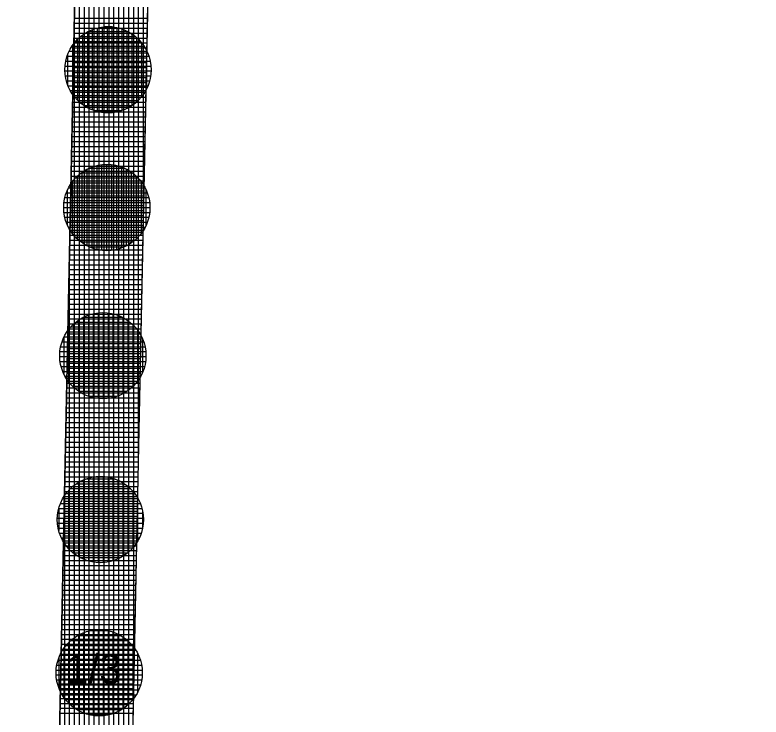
# Model space of a CAD drawing. Extents: x -566461 to -565198, y -1096301 to -1095707.
# Drawn here: x -565645.08 to -565614.79, y -1095920.77 to -1095892.27 of the extents above; entities that cross this region are included whole.
import ezdxf

# ---------------------------------------------------------------- set-up
doc = ezdxf.new("R2010")
doc.units = 0
for name, color, linetype in [('Vrstva 1', 7, 'Continuous'), ('Vrstva 40', 7, 'Continuous'), ('Vrstva 43', 7, 'Continuous'), ('Vrstva 44', 7, 'Continuous')]:
    doc.layers.add(name, color=color, linetype=linetype)

msp = doc.modelspace()

# ---------------------------------------------------------------- linework, layer by layer
at = {"layer": 'Vrstva 1'}
for p, q in [((-565645.08, -1096008.78), (-565642.52, -1095885.6)), ((-565642.11, -1096010.51), (-565639.56, -1095885.89))]:
    msp.add_line(p, q, dxfattribs=at)
at = {"layer": 'Vrstva 43'}
for p, q in [((-565642.06, -1096008.067), (-565642.06, -1095870.575)), ((-565641.86, -1095998.292), (-565641.86, -1095870.594)), ((-565641.66, -1095988.518), (-565641.66, -1095870.614)), ((-565641.46, -1095978.744), (-565641.46, -1095870.633)), ((-565641.26, -1095968.97), (-565641.26, -1095870.653)), ((-565641.06, -1095959.196), (-565641.06, -1095870.672)), ((-565640.86, -1095949.422), (-565640.86, -1095870.692)), ((-565640.66, -1095939.648), (-565640.66, -1095870.711)), ((-565640.46, -1095929.874), (-565640.46, -1095870.731)), ((-565640.26, -1095920.099), (-565640.26, -1095870.75)), ((-565640.06, -1095910.325), (-565640.06, -1095870.77)), ((-565639.86, -1095900.551), (-565639.86, -1095870.789)), ((-565642.26, -1096010.423), (-565642.26, -1095872.986)), ((-565642.46, -1096010.306), (-565642.46, -1095882.689)), ((-565642.662, -1095892.41), (-565639.693, -1095892.41)), ((-565642.66, -1096010.19), (-565642.66, -1095892.336)), ((-565642.666, -1095892.61), (-565639.698, -1095892.61)), ((-565642.674, -1095893.01), (-565639.706, -1095893.01)), ((-565642.67, -1095892.81), (-565639.702, -1095892.81)), ((-565642.678, -1095893.21), (-565639.71, -1095893.21)), ((-565642.686, -1095893.61), (-565639.718, -1095893.61)), ((-565642.682, -1095893.41), (-565639.714, -1095893.41)), ((-565642.691, -1095893.81), (-565639.722, -1095893.81)), ((-565642.699, -1095894.21), (-565639.73, -1095894.21)), ((-565642.695, -1095894.01), (-565639.726, -1095894.01)), ((-565642.703, -1095894.41), (-565639.734, -1095894.41)), ((-565642.711, -1095894.81), (-565639.743, -1095894.81)), ((-565642.707, -1095894.61), (-565639.738, -1095894.61)), ((-565642.716, -1095895.01), (-565639.747, -1095895.01)), ((-565642.724, -1095895.41), (-565639.755, -1095895.41)), ((-565642.72, -1095895.21), (-565639.751, -1095895.21)), ((-565642.728, -1095895.61), (-565639.759, -1095895.61)), ((-565642.736, -1095896.01), (-565639.767, -1095896.01)), ((-565642.732, -1095895.81), (-565639.763, -1095895.81)), ((-565642.741, -1095896.21), (-565639.771, -1095896.21)), ((-565642.749, -1095896.61), (-565639.779, -1095896.61)), ((-565642.745, -1095896.41), (-565639.775, -1095896.41)), ((-565642.753, -1095896.81), (-565639.783, -1095896.81)), ((-565642.761, -1095897.21), (-565639.792, -1095897.21)), ((-565642.757, -1095897.01), (-565639.788, -1095897.01)), ((-565642.765, -1095897.41), (-565639.796, -1095897.41)), ((-565642.774, -1095897.81), (-565639.804, -1095897.81)), ((-565642.77, -1095897.61), (-565639.8, -1095897.61)), ((-565642.778, -1095898.01), (-565639.808, -1095898.01)), ((-565642.786, -1095898.41), (-565639.816, -1095898.41)), ((-565642.782, -1095898.21), (-565639.812, -1095898.21)), ((-565642.79, -1095898.61), (-565639.82, -1095898.61)), ((-565642.799, -1095899.01), (-565639.828, -1095899.01)), ((-565642.795, -1095898.81), (-565639.824, -1095898.81)), ((-565642.803, -1095899.21), (-565639.833, -1095899.21)), ((-565642.811, -1095899.61), (-565639.841, -1095899.61)), ((-565642.807, -1095899.41), (-565639.837, -1095899.41)), ((-565642.815, -1095899.81), (-565639.845, -1095899.81)), ((-565642.824, -1095900.21), (-565639.853, -1095900.21)), ((-565642.819, -1095900.01), (-565639.849, -1095900.01)), ((-565642.832, -1095900.61), (-565639.861, -1095900.61)), ((-565642.828, -1095900.41), (-565639.857, -1095900.41)), ((-565642.836, -1095900.81), (-565639.865, -1095900.81)), ((-565642.844, -1095901.21), (-565639.873, -1095901.21)), ((-565642.84, -1095901.01), (-565639.869, -1095901.01)), ((-565642.849, -1095901.41), (-565639.878, -1095901.41)), ((-565642.857, -1095901.81), (-565639.886, -1095901.81)), ((-565642.853, -1095901.61), (-565639.882, -1095901.61)), ((-565642.861, -1095902.01), (-565639.89, -1095902.01)), ((-565642.86, -1096010.073), (-565642.86, -1095901.96)), ((-565642.869, -1095902.41), (-565639.898, -1095902.41)), ((-565642.865, -1095902.21), (-565639.894, -1095902.21)), ((-565642.874, -1095902.61), (-565639.902, -1095902.61)), ((-565642.882, -1095903.01), (-565639.91, -1095903.01)), ((-565642.878, -1095902.81), (-565639.906, -1095902.81)), ((-565642.886, -1095903.21), (-565639.914, -1095903.21)), ((-565642.894, -1095903.61), (-565639.923, -1095903.61)), ((-565642.89, -1095903.41), (-565639.918, -1095903.41)), ((-565642.898, -1095903.81), (-565639.927, -1095903.81)), ((-565642.907, -1095904.21), (-565639.935, -1095904.21)), ((-565642.903, -1095904.01), (-565639.931, -1095904.01)), ((-565642.911, -1095904.41), (-565639.939, -1095904.41)), ((-565642.919, -1095904.81), (-565639.947, -1095904.81)), ((-565642.915, -1095904.61), (-565639.943, -1095904.61)), ((-565642.923, -1095905.01), (-565639.951, -1095905.01)), ((-565642.932, -1095905.41), (-565639.959, -1095905.41)), ((-565642.928, -1095905.21), (-565639.955, -1095905.21)), ((-565642.936, -1095905.61), (-565639.964, -1095905.61)), ((-565642.944, -1095906.01), (-565639.972, -1095906.01)), ((-565642.94, -1095905.81), (-565639.968, -1095905.81)), ((-565642.948, -1095906.21), (-565639.976, -1095906.21)), ((-565642.957, -1095906.61), (-565639.984, -1095906.61)), ((-565642.952, -1095906.41), (-565639.98, -1095906.41)), ((-565642.961, -1095906.81), (-565639.988, -1095906.81)), ((-565642.969, -1095907.21), (-565639.996, -1095907.21)), ((-565642.965, -1095907.01), (-565639.992, -1095907.01)), ((-565642.973, -1095907.41), (-565640, -1095907.41)), ((-565642.982, -1095907.81), (-565640.009, -1095907.81)), ((-565642.977, -1095907.61), (-565640.004, -1095907.61)), ((-565642.986, -1095908.01), (-565640.013, -1095908.01)), ((-565642.994, -1095908.41), (-565640.021, -1095908.41)), ((-565642.99, -1095908.21), (-565640.017, -1095908.21)), ((-565642.998, -1095908.61), (-565640.025, -1095908.61)), ((-565643.007, -1095909.01), (-565640.033, -1095909.01)), ((-565643.002, -1095908.81), (-565640.029, -1095908.81)), ((-565643.011, -1095909.21), (-565640.037, -1095909.21)), ((-565643.019, -1095909.61), (-565640.045, -1095909.61)), ((-565643.015, -1095909.41), (-565640.041, -1095909.41)), ((-565643.023, -1095909.81), (-565640.049, -1095909.81)), ((-565643.031, -1095910.21), (-565640.058, -1095910.21)), ((-565643.027, -1095910.01), (-565640.054, -1095910.01)), ((-565643.036, -1095910.41), (-565640.062, -1095910.41)), ((-565643.044, -1095910.81), (-565640.07, -1095910.81)), ((-565643.04, -1095910.61), (-565640.066, -1095910.61)), ((-565643.052, -1095911.21), (-565640.078, -1095911.21)), ((-565643.048, -1095911.01), (-565640.074, -1095911.01)), ((-565643.056, -1095911.41), (-565640.082, -1095911.41)), ((-565643.065, -1095911.81), (-565640.09, -1095911.81)), ((-565643.061, -1095911.61), (-565640.086, -1095911.61)), ((-565643.06, -1096009.957), (-565643.06, -1095911.583)), ((-565643.069, -1095912.01), (-565640.094, -1095912.01)), ((-565643.077, -1095912.41), (-565640.103, -1095912.41)), ((-565643.073, -1095912.21), (-565640.099, -1095912.21)), ((-565643.081, -1095912.61), (-565640.107, -1095912.61)), ((-565643.09, -1095913.01), (-565640.115, -1095913.01)), ((-565643.085, -1095912.81), (-565640.111, -1095912.81)), ((-565643.094, -1095913.21), (-565640.119, -1095913.21)), ((-565643.102, -1095913.61), (-565640.127, -1095913.61)), ((-565643.098, -1095913.41), (-565640.123, -1095913.41)), ((-565643.106, -1095913.81), (-565640.131, -1095913.81)), ((-565643.115, -1095914.21), (-565640.139, -1095914.21)), ((-565643.11, -1095914.01), (-565640.135, -1095914.01)), ((-565643.119, -1095914.41), (-565640.144, -1095914.41)), ((-565643.127, -1095914.81), (-565640.152, -1095914.81)), ((-565643.123, -1095914.61), (-565640.148, -1095914.61)), ((-565643.131, -1095915.01), (-565640.156, -1095915.01)), ((-565643.14, -1095915.41), (-565640.164, -1095915.41)), ((-565643.135, -1095915.21), (-565640.16, -1095915.21)), ((-565643.144, -1095915.61), (-565640.168, -1095915.61)), ((-565643.152, -1095916.01), (-565640.176, -1095916.01)), ((-565643.148, -1095915.81), (-565640.172, -1095915.81)), ((-565643.156, -1095916.21), (-565640.18, -1095916.21)), ((-565643.164, -1095916.61), (-565640.189, -1095916.61)), ((-565643.16, -1095916.41), (-565640.185, -1095916.41)), ((-565643.169, -1095916.81), (-565640.193, -1095916.81)), ((-565643.177, -1095917.21), (-565640.201, -1095917.21)), ((-565643.173, -1095917.01), (-565640.197, -1095917.01)), ((-565643.181, -1095917.41), (-565640.205, -1095917.41)), ((-565643.189, -1095917.81), (-565640.213, -1095917.81)), ((-565643.185, -1095917.61), (-565640.209, -1095917.61)), ((-565643.194, -1095918.01), (-565640.217, -1095918.01)), ((-565643.202, -1095918.41), (-565640.225, -1095918.41)), ((-565643.198, -1095918.21), (-565640.221, -1095918.21)), ((-565643.206, -1095918.61), (-565640.23, -1095918.61)), ((-565643.214, -1095919.01), (-565640.238, -1095919.01)), ((-565643.21, -1095918.81), (-565640.234, -1095918.81)), ((-565643.219, -1095919.21), (-565640.242, -1095919.21)), ((-565643.227, -1095919.61), (-565640.25, -1095919.61)), ((-565643.223, -1095919.41), (-565640.246, -1095919.41)), ((-565643.231, -1095919.81), (-565640.254, -1095919.81)), ((-565643.239, -1095920.21), (-565640.262, -1095920.21)), ((-565643.235, -1095920.01), (-565640.258, -1095920.01)), ((-565643.243, -1095920.41), (-565640.266, -1095920.41)), ((-565643.248, -1095920.61), (-565640.27, -1095920.61))]:
    msp.add_line(p, q, dxfattribs=at)
msp.add_lwpolyline([(-565639.56, -1095885.89), (-565630.78, -1095886.75), (-565609.49, -1095886.27), (-565595.88, -1095884.74), (-565585.92, -1095883.62), (-565568.01, -1095880.69), (-565521.32, -1095878.21), (-565519.36, -1095863.08), (-565522.03, -1095863.23), (-565569.62, -1095865.76), (-565587.97, -1095868.76), (-565610.5, -1095871.29), (-565630.22, -1095871.73), (-565642.21, -1095870.56), (-565642.52, -1095885.6), (-565645.08, -1096008.78), (-565642.11, -1096010.51)], close=True, dxfattribs=at)
at = {"layer": 'Vrstva 44'}
for p, q in [((-565642.14, -1095892.967), (-565642.14, -1095896.034)), ((-565640.469, -1095892.96), (-565642.128, -1095892.96)), ((-565641.94, -1095892.872), (-565641.94, -1095896.128)), ((-565641.74, -1095892.808), (-565641.74, -1095896.193)), ((-565641.54, -1095892.768), (-565641.54, -1095896.232)), ((-565641.117, -1095892.76), (-565641.475, -1095892.76)), ((-565641.34, -1095892.752), (-565641.34, -1095896.249)), ((-565641.14, -1095892.759), (-565641.14, -1095896.241)), ((-565640.94, -1095892.788), (-565640.94, -1095896.211)), ((-565640.74, -1095892.844), (-565640.74, -1095896.156)), ((-565640.54, -1095892.926), (-565640.54, -1095896.076)), ((-565640.34, -1095893.037), (-565640.34, -1095895.961)), ((-565642.54, -1095893.268), (-565642.54, -1095895.733)), ((-565640.176, -1095893.16), (-565642.423, -1095893.16)), ((-565642.34, -1095893.094), (-565642.34, -1095895.905)), ((-565640.14, -1095893.192), (-565640.14, -1095895.809)), ((-565639.826, -1095893.56), (-565642.774, -1095893.56)), ((-565642.74, -1095893.508), (-565642.74, -1095895.493)), ((-565639.974, -1095893.36), (-565642.626, -1095893.36)), ((-565639.94, -1095893.4), (-565639.94, -1095895.598)), ((-565642.94, -1095893.892), (-565642.94, -1095895.106)), ((-565639.716, -1095893.76), (-565642.886, -1095893.76)), ((-565639.74, -1095893.711), (-565639.74, -1095895.29)), ((-565639.585, -1095894.16), (-565643.015, -1095894.16)), ((-565639.635, -1095893.96), (-565642.963, -1095893.96)), ((-565639.558, -1095894.36), (-565643.043, -1095894.36)), ((-565639.553, -1095894.56), (-565643.048, -1095894.56)), ((-565639.571, -1095894.76), (-565643.03, -1095894.76)), ((-565639.612, -1095894.96), (-565642.987, -1095894.96)), ((-565639.681, -1095895.16), (-565642.919, -1095895.16)), ((-565639.778, -1095895.36), (-565642.824, -1095895.36)), ((-565639.908, -1095895.56), (-565642.69, -1095895.56)), ((-565640.088, -1095895.76), (-565642.514, -1095895.76)), ((-565640.339, -1095895.96), (-565642.264, -1095895.96)), ((-565640.752, -1095896.16), (-565641.848, -1095896.16)), ((-565641.96, -1095898.451), (-565641.96, -1095901.729)), ((-565641.76, -1095898.391), (-565641.76, -1095901.791)), ((-565641.56, -1095898.355), (-565641.56, -1095901.827)), ((-565641.36, -1095898.341), (-565641.36, -1095901.839)), ((-565641.16, -1095898.35), (-565641.16, -1095901.828)), ((-565640.96, -1095898.385), (-565640.96, -1095901.794)), ((-565640.76, -1095898.445), (-565640.76, -1095901.737)), ((-565640.29, -1095898.7), (-565642.413, -1095898.7)), ((-565642.36, -1095898.663), (-565642.36, -1095901.517)), ((-565642.16, -1095898.54), (-565642.16, -1095901.641)), ((-565640.623, -1095898.5), (-565642.077, -1095898.5)), ((-565640.56, -1095898.53), (-565640.56, -1095901.65)), ((-565640.36, -1095898.648), (-565640.36, -1095901.531)), ((-565639.907, -1095899.1), (-565642.791, -1095899.1)), ((-565642.76, -1095899.054), (-565642.76, -1095901.124)), ((-565640.07, -1095898.9), (-565642.631, -1095898.9)), ((-565642.56, -1095898.827), (-565642.56, -1095901.354)), ((-565640.16, -1095898.809), (-565640.16, -1095901.372)), ((-565639.96, -1095899.03), (-565639.96, -1095901.152)), ((-565639.791, -1095899.3), (-565642.91, -1095899.3)), ((-565639.76, -1095899.362), (-565639.76, -1095900.818)), ((-565639.645, -1095899.7), (-565643.055, -1095899.7)), ((-565639.704, -1095899.5), (-565642.997, -1095899.5)), ((-565642.96, -1095899.409), (-565642.96, -1095900.772)), ((-565639.611, -1095899.9), (-565643.088, -1095899.9)), ((-565639.602, -1095900.1), (-565643.098, -1095900.1)), ((-565639.615, -1095900.3), (-565643.086, -1095900.3)), ((-565639.65, -1095900.5), (-565643.051, -1095900.5)), ((-565639.71, -1095900.7), (-565642.988, -1095900.7)), ((-565639.801, -1095900.9), (-565642.899, -1095900.9)), ((-565639.923, -1095901.1), (-565642.779, -1095901.1)), ((-565640.088, -1095901.3), (-565642.612, -1095901.3)), ((-565640.314, -1095901.5), (-565642.383, -1095901.5)), ((-565640.669, -1095901.7), (-565642.033, -1095901.7)), ((-565640.699, -1095904.55), (-565642.32, -1095904.55)), ((-565642.3, -1095904.539), (-565642.3, -1095907.661)), ((-565642.1, -1095904.454), (-565642.1, -1095907.746)), ((-565641.9, -1095904.396), (-565641.9, -1095907.806)), ((-565641.7, -1095904.362), (-565641.7, -1095907.839)), ((-565641.5, -1095904.351), (-565641.5, -1095907.848)), ((-565641.3, -1095904.363), (-565641.3, -1095907.835)), ((-565641.1, -1095904.401), (-565641.1, -1095907.8)), ((-565640.9, -1095904.462), (-565640.9, -1095907.74)), ((-565640.7, -1095904.55), (-565640.7, -1095907.649)), ((-565642.7, -1095904.817), (-565642.7, -1095907.382)), ((-565640.397, -1095904.75), (-565642.621, -1095904.75)), ((-565642.5, -1095904.659), (-565642.5, -1095907.541)), ((-565640.5, -1095904.673), (-565640.5, -1095907.527)), ((-565640.3, -1095904.837), (-565640.3, -1095907.362)), ((-565640.042, -1095905.15), (-565642.977, -1095905.15)), ((-565642.9, -1095905.039), (-565642.9, -1095907.16)), ((-565640.193, -1095904.95), (-565642.828, -1095904.95)), ((-565640.1, -1095905.066), (-565640.1, -1095907.135)), ((-565643.1, -1095905.37), (-565643.1, -1095906.83)), ((-565639.931, -1095905.35), (-565643.091, -1095905.35)), ((-565639.9, -1095905.416), (-565639.9, -1095906.781)), ((-565639.797, -1095905.75), (-565643.223, -1095905.75)), ((-565639.849, -1095905.55), (-565643.17, -1095905.55)), ((-565639.768, -1095905.95), (-565643.252, -1095905.95)), ((-565639.763, -1095906.15), (-565643.258, -1095906.15)), ((-565639.779, -1095906.35), (-565643.242, -1095906.35)), ((-565639.819, -1095906.55), (-565643.199, -1095906.55)), ((-565639.887, -1095906.75), (-565643.133, -1095906.75)), ((-565639.983, -1095906.95), (-565643.039, -1095906.95)), ((-565640.11, -1095907.15), (-565642.908, -1095907.15)), ((-565640.288, -1095907.35), (-565642.734, -1095907.35)), ((-565640.534, -1095907.55), (-565642.487, -1095907.55)), ((-565640.93, -1095907.75), (-565642.087, -1095907.75)), ((-565642.3, -1095911.144), (-565642.3, -1095914.357)), ((-565641.005, -1095911.11), (-565642.218, -1095911.11)), ((-565642.1, -1095911.071), (-565642.1, -1095914.43)), ((-565641.9, -1095911.025), (-565641.9, -1095914.474)), ((-565641.7, -1095911.004), (-565641.7, -1095914.496)), ((-565641.5, -1095911.005), (-565641.5, -1095914.496)), ((-565641.3, -1095911.029), (-565641.3, -1095914.471)), ((-565641.1, -1095911.076), (-565641.1, -1095914.422)), ((-565640.9, -1095911.152), (-565640.9, -1095914.348)), ((-565640.376, -1095911.51), (-565642.842, -1095911.51)), ((-565642.7, -1095911.382), (-565642.7, -1095914.119)), ((-565640.617, -1095911.31), (-565642.601, -1095911.31)), ((-565642.5, -1095911.245), (-565642.5, -1095914.255)), ((-565640.7, -1095911.257), (-565640.7, -1095914.245)), ((-565640.5, -1095911.397), (-565640.5, -1095914.1)), ((-565640.205, -1095911.71), (-565643.017, -1095911.71)), ((-565642.9, -1095911.569), (-565642.9, -1095913.93)), ((-565640.3, -1095911.592), (-565640.3, -1095913.909)), ((-565639.983, -1095912.11), (-565643.237, -1095912.11)), ((-565640.075, -1095911.91), (-565643.143, -1095911.91)), ((-565643.1, -1095911.835), (-565643.1, -1095913.664)), ((-565640.1, -1095911.868), (-565640.1, -1095913.632)), ((-565639.918, -1095912.31), (-565643.303, -1095912.31)), ((-565643.3, -1095912.3), (-565643.3, -1095913.198)), ((-565639.9, -1095912.38), (-565639.9, -1095913.113)), ((-565639.861, -1095912.71), (-565643.358, -1095912.71)), ((-565639.878, -1095912.51), (-565643.343, -1095912.51)), ((-565639.869, -1095912.91), (-565643.351, -1095912.91)), ((-565639.899, -1095913.11), (-565643.321, -1095913.11)), ((-565639.954, -1095913.31), (-565643.268, -1095913.31)), ((-565640.034, -1095913.51), (-565643.185, -1095913.51)), ((-565640.149, -1095913.71), (-565643.071, -1095913.71)), ((-565640.301, -1095913.91), (-565642.919, -1095913.91)), ((-565640.512, -1095914.11), (-565642.71, -1095914.11)), ((-565640.82, -1095914.31), (-565642.402, -1095914.31)), ((-565641.252, -1095917.27), (-565642.067, -1095917.27)), ((-565641.9, -1095917.238), (-565641.9, -1095920.702)), ((-565641.7, -1095917.222), (-565641.7, -1095920.719)), ((-565641.5, -1095917.229), (-565641.5, -1095920.711)), ((-565641.3, -1095917.258), (-565641.3, -1095920.681)), ((-565642.7, -1095917.564), (-565642.7, -1095920.375)), ((-565640.762, -1095917.47), (-565642.559, -1095917.47)), ((-565642.5, -1095917.437), (-565642.5, -1095920.504)), ((-565642.3, -1095917.342), (-565642.3, -1095920.598)), ((-565642.1, -1095917.278), (-565642.1, -1095920.663)), ((-565641.1, -1095917.314), (-565641.1, -1095920.626)), ((-565640.9, -1095917.396), (-565640.9, -1095920.546)), ((-565640.7, -1095917.507), (-565640.7, -1095920.431)), ((-565640.3, -1095917.87), (-565643.019, -1095917.87)), ((-565642.9, -1095917.738), (-565642.9, -1095920.203)), ((-565640.491, -1095917.67), (-565642.83, -1095917.67)), ((-565640.5, -1095917.662), (-565640.5, -1095920.279)), ((-565640.3, -1095917.87), (-565640.3, -1095920.068)), ((-565640.161, -1095918.07), (-565643.16, -1095918.07)), ((-565643.1, -1095917.978), (-565643.1, -1095919.963)), ((-565640.1, -1095918.181), (-565640.1, -1095919.76)), ((-565639.984, -1095918.47), (-565643.335, -1095918.47)), ((-565643.3, -1095918.362), (-565643.3, -1095919.576)), ((-565640.056, -1095918.27), (-565643.262, -1095918.27)), ((-565639.938, -1095918.67), (-565643.383, -1095918.67)), ((-565639.915, -1095918.87), (-565643.407, -1095918.87)), ((-565639.914, -1095919.07), (-565643.406, -1095919.07)), ((-565639.937, -1095919.27), (-565643.382, -1095919.27)), ((-565639.985, -1095919.47), (-565643.335, -1095919.47)), ((-565640.058, -1095919.67), (-565643.263, -1095919.67)), ((-565640.16, -1095919.87), (-565643.159, -1095919.87)), ((-565640.301, -1095920.07), (-565643.019, -1095920.07)), ((-565640.489, -1095920.27), (-565642.829, -1095920.27)), ((-565640.759, -1095920.47), (-565642.558, -1095920.47)), ((-565641.251, -1095920.67), (-565642.072, -1095920.67))]:
    msp.add_line(p, q, dxfattribs=at)
for centre in [(-565641.3, -1095894.5), (-565641.35, -1095900.09), (-565641.51, -1095906.1), (-565641.61, -1095912.75), (-565641.66, -1095918.97)]:
    msp.add_circle(centre, 1.75, dxfattribs=at)

# ---------------------------------------------------------------- texts
at = {"layer": 'Vrstva 40'}
msp.add_text('1/3', height=1.2, dxfattribs=at).set_placement((-565642.99, -1095919.41))

doc.saveas('drawing.dxf')
